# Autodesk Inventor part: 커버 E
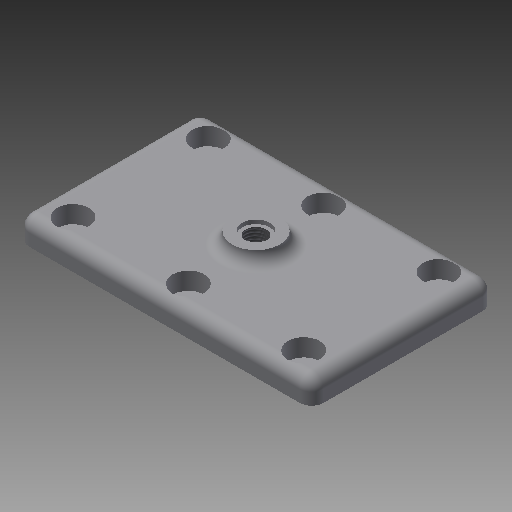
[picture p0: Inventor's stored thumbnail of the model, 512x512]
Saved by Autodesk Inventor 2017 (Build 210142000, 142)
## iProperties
Created: 2020-04
Part Number: 커버 E
Material: 알루미늄 6061
Document SubType Name: Modeling
Designer: mduedu
Density: 2.71 g/cm^3
Appearance: 기본값
Mass: 58.8274 g
Surface Area: 89.9597 cm^2
Volume: 21.7075 cm^3
Author: mduedu
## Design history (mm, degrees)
sketch "스케치1"
  geometry: L1 (37, 23)-(-37, 23); L2 (-37, 23)-(-37, -23); L3 (-37, -23)-(37, -23); L4 (37, -23)-(37, 23); L5 (37, 23)-(-37, -23); L6 (-37, 23)-(37, -23); 1 further point
  constraints: 12 end point, 2 midpoint, 2 parallel, 1 horizontal, 1 perpendicular
  dimensions: "d0" = 74 distance of L3.end L2.end; "d1" = 46 distance of L2.end L1.end
extrude "돌출1" new body sketch "스케치1" distance "d2" = 6; taper "d3" = 0 deg
sketch "스케치2"
  geometry: C1 r 6 at (0, 0); 1 further point
  constraints: 1 centre point, 1 coincident
  dimensions: "d4" = 12 diameter of C1
extrude "돌출2" join sketch "스케치2" distance "d5" = 3; taper "d6" = 0 deg
fillet "모깎기1" dims "d7" = 3
fillet "모깎기2" dims "d8" = 3
fillet "모깎기3" dims "d9" = 3
sketch "스케치3"
  geometry: L1 (-30, -13)-(30, -13); L2 (30, -13)-(30, 13); L3 (30, 13)-(-30, 13); L4 (-30, 13)-(-30, -13); L5 (-30, -13)-(30, 13); L6 (30, -13)-(-30, 13); 1 further point
  constraints: 12 end point, 2 midpoint, 2 parallel, 1 horizontal, 1 perpendicular
  dimensions: "d10" = 60 distance of L3.end L2.end; "d11" = 26 distance of L2.end L1.end
extrude "돌출3" join sketch "스케치3" distance "d12" = 2; taper "d13" = 0 deg
fillet "모깎기4" dims "d14" = 3
chamfer "모따기1" distance "d15" = 0.5; stored, may be unused: second distance "d16" = 2, angle "d17" = 45 deg
sketch "스케치4"
  geometry: L1 (-29, -17)-(29, -17); L2 (29, -17)-(29, 17); L3 (29, 17)-(-29, 17); L4 (-29, 17)-(-29, -17); L5 (-29, -17)-(29, 17); L6 (29, -17)-(-29, 17); 7 further points
  constraints: 12 end point, 4 coincident, 4 midpoint, 2 parallel, 1 horizontal, 1 perpendicular
  dimensions: "d18" = 58 distance of L3.end L2.end; "d19" = 34 distance of L2.end L1.end
hole "구멍1" sketch "스케치4" at (-29, 17), (-29, -17), (29, -17), (29, 17), (0, 17), (0, -17) diameter "d20" = 4.5; stored, may be unused: countersink angle "d24" = 90 deg, drill point angle "d26" = 118 deg; dims "d21" = 6, "d22" = 8, "d23" = 4.4, "d25" = 8
hole "구멍2" diameter "d29" = 5.188; stored, may be unused: countersink angle "d33" = 90 deg, drill point angle "d35" = 118 deg; dims "d27" = 10, "d28" = 10, "d30" = 6, "d31" = 8, "d32" = 4.4, "d34" = 8
sketch "스케치5"
  geometry: C1 r 3.5 at (0, 0); 1 further point
  constraints: 1 centre point, 1 coincident
  dimensions: "d36" = 7 diameter of C1
extrude "돌출4" cut sketch "스케치5" distance "d37" = 1; taper "d38" = 0 deg
node "솔리드1"
